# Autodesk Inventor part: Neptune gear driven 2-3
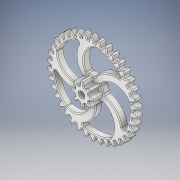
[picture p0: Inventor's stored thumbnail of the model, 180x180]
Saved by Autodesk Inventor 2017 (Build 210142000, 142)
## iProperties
Created: 2016-07
Part Number: Neptune gear driven 2-3
Material: Generic
Document SubType Name: Modeling
Designer: Stan
Density: 1 g/cm^3
Appearance: White
Author: Stan
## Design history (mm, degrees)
sketch "Sketch1"
  geometry: A1 r 17.883 centre (-8.66, -36.284) between (-25.106, -29.261) and (-26.3, -33.348); A2 r 17.883 centre (-8.66, -36.284) between (-25.106, -29.261) and (-26.3, -33.348); A3 r 17.883 centre (-35.099, -12.634) between (-30.223, -29.839) and (-26.293, -28.198); A4 r 17.883 centre (-35.099, -12.634) between (-30.223, -29.839) and (-26.293, -28.198); A5 r 17.883 centre (-2.57, -37.214) between (-19.947, -32.994) and (-20.452, -37.222); A6 r 17.883 centre (-2.57, -37.214) between (-19.947, -32.994) and (-20.452, -37.222); A7 r 17.883 centre (-32.54, -18.238) between (-24.899, -34.406) and (-21.293, -32.141); A8 r 17.883 centre (-32.54, -18.238) between (-24.899, -34.406) and (-21.293, -32.141); A9 r 17.883 centre (3.591, -37.13) between (-14.244, -35.827) and (-14.047, -40.081); A10 r 17.883 centre (3.591, -37.13) between (-14.244, -35.827) and (-14.047, -40.081); A11 r 17.883 centre (-29.095, -23.346) between (-18.896, -38.035) and (-15.713, -35.208); A12 r 17.883 centre (-29.095, -23.346) between (-18.896, -38.035) and (-15.713, -35.208); A13 r 17.883 centre (9.653, -36.032) between (-8.153, -37.683) and (-7.258, -41.846); A14 r 17.883 centre (9.653, -36.032) between (-8.153, -37.683) and (-7.258, -41.846); A15 r 17.883 centre (-24.855, -27.816) between (-12.378, -40.627) and (-9.703, -37.314); A16 r 17.883 centre (-24.855, -27.816) between (-12.378, -40.627) and (-9.703, -37.314); A17 r 17.883 centre (15.452, -33.952) between (-1.839, -38.511) and (-0.271, -42.47); A18 r 17.883 centre (15.452, -33.952) between (-1.839, -38.511) and (-0.271, -42.47); A19 r 17.883 centre (-19.938, -31.528) between (-5.523, -42.11) and (-3.429, -38.402); A20 r 17.883 centre (-19.938, -31.528) between (-5.523, -42.11) and (-3.429, -38.402); A21 r 17.883 centre (20.83, -30.946) between (4.524, -38.288) and (6.723, -41.935); A22 r 17.883 centre (20.83, -30.946) between (4.524, -38.288) and (6.723, -41.935); A23 r 17.883 centre (-14.477, -34.379) between (1.484, -42.445) and (2.938, -38.443); A24 r 17.883 centre (-14.477, -34.379) between (1.484, -42.445) and (2.938, -38.443); A25 r 17.883 centre (25.639, -27.095) between (10.765, -37.022) and (13.533, -40.257); A26 r 17.883 centre (25.639, -27.095) between (10.765, -37.022) and (13.533, -40.257); A27 r 17.883 centre (-8.621, -36.293) between (8.45, -41.622) and (9.226, -37.435); A28 r 17.883 centre (-8.621, -36.293) between (8.45, -41.622) and (9.226, -37.435); A29 r 17.883 centre (29.749, -22.506) between (16.711, -34.745) and (19.975, -37.48); A30 r 17.883 centre (29.749, -22.506) between (16.711, -34.745) and (19.975, -37.48); A31 r 17.883 centre (-2.529, -37.217) between (15.185, -39.663) and (15.261, -35.406); A32 r 17.883 centre (-2.529, -37.217) between (15.185, -39.663) and (15.261, -35.406); A33 r 17.883 centre (33.048, -17.302) between (22.202, -31.52) and (25.871, -33.681); A34 r 17.883 centre (33.048, -17.302) between (22.202, -31.52) and (25.871, -33.681); A35 r 17.883 centre (3.631, -37.126) between (21.506, -36.623) and (20.881, -32.411); A36 r 17.883 centre (3.631, -37.126) between (21.506, -36.623) and (20.881, -32.411); A37 r 17.883 centre (35.445, -11.627) between (27.088, -27.436) and (31.062, -28.964); A38 r 17.883 centre (35.445, -11.627) between (27.088, -27.436) and (31.062, -28.964); A39 r 17.883 centre (9.692, -36.022) between (27.241, -32.584) and (25.931, -28.532); A40 r 17.883 centre (9.692, -36.022) between (27.241, -32.584) and (25.931, -28.532); A41 r 17.883 centre (8.621, 36.293) between (-8.45, 41.622) and (-9.226, 37.435); A42 r 17.883 centre (-25.639, 27.095) between (-10.765, 37.022) and (-13.533, 40.257); A43 r 17.883 centre (2.529, 37.217) between (-15.185, 39.663) and (-15.261, 35.406); A44 r 17.883 centre (-29.749, 22.506) between (-16.711, 34.745) and (-19.975, 37.48); A45 r 17.883 centre (-3.631, 37.126) between (-21.506, 36.623) and (-20.881, 32.411); A46 r 17.883 centre (-33.048, 17.302) between (-22.202, 31.52) and (-25.871, 33.681); A47 r 17.883 centre (-9.692, 36.022) between (-27.241, 32.584) and (-25.931, 28.532); A48 r 17.883 centre (-35.445, 11.627) between (-27.088, 27.436) and (-31.062, 28.964); A49 r 17.883 centre (-15.489, 33.935) between (-32.233, 27.655) and (-30.273, 23.875); A50 r 17.883 centre (-36.875, 5.634) between (-31.234, 22.603) and (-35.406, 23.456); A51 r 17.883 centre (-20.863, 30.923) between (-36.345, 21.973) and (-33.79, 18.566); A52 r 17.883 centre (-37.3, -0.512) between (-34.528, 17.154) and (-38.784, 17.309); A53 r 17.883 centre (-25.669, 27.067) between (-39.466, 15.691) and (-36.385, 12.752); A54 r 17.883 centre (-36.706, -6.645) between (-36.881, 11.237) and (-41.104, 10.689); A55 r 17.883 centre (-29.774, 22.473) between (-41.51, 8.981) and (-37.988, 6.589); A56 r 17.883 centre (-35.112, -12.596) between (-38.228, 5.013) and (-42.302, 3.778); A57 r 17.883 centre (-33.067, 17.266) between (-42.422, 2.026) and (-38.554, 0.246); A58 r 17.883 centre (-32.56, -18.203) between (-38.531, -1.347) and (-42.347, -3.237); A59 r 17.883 centre (-35.457, 11.588) between (-42.177, -4.984) and (-38.069, -6.103); A60 r 17.883 centre (-29.12, -23.314) between (-37.784, -7.671) and (-41.237, -10.163); A61 r 17.883 centre (-36.881, 5.594) between (-40.782, -11.858) and (-36.545, -12.285); A62 r 17.883 centre (-24.885, -27.789) between (-36.006, -13.785) and (-39.002, -16.811); A63 r 17.883 centre (-37.299, -0.553) between (-38.274, -18.409) and (-34.025, -18.133); A64 r 17.883 centre (-19.972, -31.506) between (-33.246, -19.524) and (-35.703, -23.002)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; 1 further point
  constraints: 404 point on circle, 202 centre point, 600 other
extrude "Extrusion1" new body sketch "Sketch1" distance "d0" = 6.35; taper "d1" = 0 deg
sketch "Sketch2"
  geometry: C1 r 3.175 at (0, 0); A1 r 6.91 centre (0, 0) between (-2.281, 6.522) and (-3.176, 6.136); A2 r 6.91 centre (0, 0) between (-6.225, 2.999) and (-6.585, 2.093); A3 r 6.91 centre (0, 0) between (-6.522, -2.281) and (-6.136, -3.176); A4 r 6.91 centre (0, 0) between (-2.999, -6.225) and (-2.093, -6.585); A5 r 6.91 centre (0, 0) between (2.281, -6.522) and (3.176, -6.136); A6 r 6.91 centre (0, 0) between (6.225, -2.999) and (6.585, -2.093); A7 r 6.91 centre (0, 0) between (6.522, 2.281) and (6.136, 3.176); A8 r 6.91 centre (0, 0) between (2.999, 6.225) and (2.093, 6.585); A9 r 12.44 centre (0.027, -1.866) between (0.826, 10.548) and (-1.126, 10.521); A10 r 7.658 centre (-6.118, 7.318) between (1.54, 7.339) and (0.826, 10.548); A11 r 7.658 centre (5.907, 7.49) between (-1.126, 10.521) and (-1.749, 7.281); A12 r 0.794 centre (2.334, 7.341) between (1.54, 7.339) and (2.093, 6.585); A13 r 0.794 centre (-2.543, 7.272) between (-2.281, 6.522) and (-1.749, 7.292); A14 r 12.44 centre (1.338, -1.301) between (-6.875, 8.043) and (-8.236, 6.643); A15 r 7.658 centre (-9.501, 0.848) between (-4.1, 6.279) and (-6.875, 8.043); A16 r 7.658 centre (-1.119, 9.473) between (-8.236, 6.643) and (-6.385, 3.912); A17 r 0.794 centre (-3.541, 6.841) between (-4.1, 6.279) and (-3.176, 6.136); A18 r 0.794 centre (-6.94, 3.344) between (-6.225, 2.999) and (-6.393, 3.92); A19 r 12.44 centre (1.866, 0.027) between (-10.548, 0.826) and (-10.521, -1.126); A20 r 7.658 centre (-7.318, -6.118) between (-7.339, 1.54) and (-10.548, 0.826); A21 r 7.658 centre (-7.49, 5.907) between (-10.521, -1.126) and (-7.281, -1.749); A22 r 0.794 centre (-7.341, 2.334) between (-7.339, 1.54) and (-6.585, 2.093); A23 r 0.794 centre (-7.272, -2.543) between (-6.522, -2.281) and (-7.292, -1.749); A24 r 12.44 centre (1.301, 1.338) between (-8.043, -6.875) and (-6.643, -8.236); A25 r 7.658 centre (-0.848, -9.501) between (-6.279, -4.1) and (-8.043, -6.875); A26 r 7.658 centre (-9.473, -1.119) between (-6.643, -8.236) and (-3.912, -6.385); A27 r 0.794 centre (-6.841, -3.541) between (-6.279, -4.1) and (-6.136, -3.176); A28 r 0.794 centre (-3.344, -6.94) between (-2.999, -6.225) and (-3.92, -6.393); A29 r 12.44 centre (-0.027, 1.866) between (-0.826, -10.548) and (1.126, -10.521); A30 r 7.658 centre (6.118, -7.318) between (-1.54, -7.339) and (-0.826, -10.548); A31 r 7.658 centre (-5.907, -7.49) between (1.126, -10.521) and (1.749, -7.281); A32 r 0.794 centre (-2.334, -7.341) between (-1.54, -7.339) and (-2.093, -6.585); A33 r 0.794 centre (2.543, -7.272) between (2.281, -6.522) and (1.749, -7.292); A34 r 12.44 centre (-1.338, 1.301) between (6.875, -8.043) and (8.236, -6.643); A35 r 7.658 centre (9.501, -0.848) between (4.1, -6.279) and (6.875, -8.043); A36 r 7.658 centre (1.119, -9.473) between (8.236, -6.643) and (6.385, -3.912); A37 r 0.794 centre (3.541, -6.841) between (4.1, -6.279) and (3.176, -6.136); A38 r 0.794 centre (6.94, -3.344) between (6.225, -2.999) and (6.393, -3.92); A39 r 12.44 centre (-1.866, -0.027) between (10.548, -0.826) and (10.521, 1.126); A40 r 7.658 centre (7.318, 6.118) between (7.339, -1.54) and (10.548, -0.826); A41 r 7.658 centre (7.49, -5.907) between (10.521, 1.126) and (7.281, 1.749); A42 r 0.794 centre (7.341, -2.334) between (7.339, -1.54) and (6.585, -2.093); A43 r 0.794 centre (7.272, 2.543) between (6.522, 2.281) and (7.292, 1.749); A44 r 12.44 centre (-1.301, -1.338) between (8.043, 6.875) and (6.643, 8.236); A45 r 7.658 centre (0.848, 9.501) between (6.279, 4.1) and (8.043, 6.875); A46 r 7.658 centre (9.473, 1.119) between (6.643, 8.236) and (3.912, 6.385); A47 r 0.794 centre (6.841, 3.541) between (6.279, 4.1) and (6.136, 3.176); A48 r 0.794 centre (3.344, 6.94) between (2.999, 6.225) and (3.92, 6.393); 1 further point
  constraints: 104 point on circle, 49 centre point, 1 coincident
extrude "Extrusion2" join sketch "Sketch2" distance "d3" = 9.525; taper "d4" = 0 deg
fillet "Fillet7" dims "d10" = 0.79375
fillet "Fillet8" dims "d11" = 0.79375
fillet "Fillet9" dims "d12" = 0.79375
fillet "Fillet11" dims "d14" = 0.79375
fillet "Fillet12" dims "d15" = 0.79375
fillet "Fillet13" dims "d16" = 1.5875
fillet "Fillet14" dims "d17" = 1.5875
fillet "Fillet15" dims "d18" = 1.5875
fillet "Fillet16" dims "d19" = 0.79375
fillet "Fillet17" dims "d20" = 0.79375
body "Solid1"
